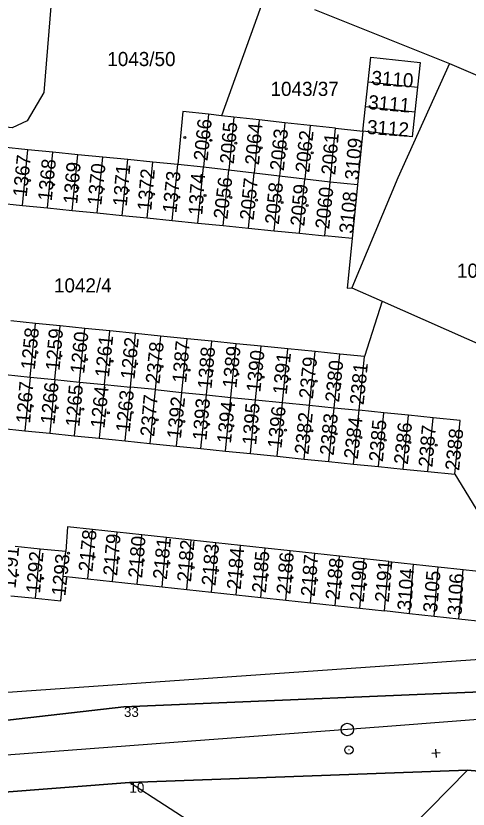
# Model space of a CAD drawing. Extents: x -779330 to -774454, y -1144748 to -1142831.
# Drawn here: x -775151 to -775096.6, y -1144462.2 to -1144366.8 of the extents above; entities that cross this region are included whole.
import ezdxf

# ---------------------------------------------------------------- set-up
doc = ezdxf.new("R2010")
doc.units = 0
for name, color, linetype in [('Hranice parcel', 7, 'Continuous'), ('Parcelní čísla', 7, 'Continuous'), ('SŽDC', 7, 'Continuous'), ('Vrstva 1', 7, 'Continuous'), ('Vrstva 53', 7, 'Continuous'), ('Vrstva 60', 7, 'Continuous'), ('Vrstva 7', 7, 'Continuous'), ('Značky budov', 7, 'Continuous')]:
    doc.layers.add(name, color=color, linetype=linetype)

msp = doc.modelspace()

# ---------------------------------------------------------------- linework, layer by layer
at = {"layer": 'Hranice parcel'}
for p, q in [((-775120.83, -1144363.72), (-775126.26, -1144378.82)), ((-775115.06, -1144366.03), (-775098.84, -1144372.52)), ((-775098.84, -1144372.52), (-775077.4, -1144381.72)), ((-775108.94, -1144377.72), (-775108.62, -1144374.75)), ((-775108.62, -1144374.75), (-775102.67, -1144375.4)), ((-775102.67, -1144375.4), (-775103, -1144378.37)), ((-775108.94, -1144377.72), (-775103, -1144378.37)), ((-775127.85, -1144378.65), (-775128.45, -1144385.01)), ((-775126.26, -1144378.82), (-775127.85, -1144378.65)), ((-775124.79, -1144378.98), (-775126.26, -1144378.82)), ((-775124.79, -1144378.98), (-775125.4, -1144385.37)), ((-775121.73, -1144379.32), (-775124.79, -1144378.98)), ((-775121.73, -1144379.32), (-775122.35, -1144385.72)), ((-775118.66, -1144379.66), (-775121.73, -1144379.32)), ((-775118.66, -1144379.66), (-775119.3, -1144386.08)), ((-775115.6, -1144379.99), (-775118.66, -1144379.66)), ((-775115.6, -1144379.99), (-775116.25, -1144386.44)), ((-775112.54, -1144380.33), (-775115.6, -1144379.99)), ((-775113.19, -1144386.79), (-775112.54, -1144380.33)), ((-775149.57, -1144382.91), (-775152.58, -1144382.61)), ((-775150.24, -1144389.6), (-775149.57, -1144382.91)), ((-775146.57, -1144383.21), (-775149.57, -1144382.91)), ((-775147.23, -1144389.91), (-775146.57, -1144383.21)), ((-775143.57, -1144383.51), (-775146.57, -1144383.21)), ((-775144.23, -1144390.21), (-775143.57, -1144383.51)), ((-775140.56, -1144383.81), (-775143.57, -1144383.51)), ((-775141.23, -1144390.51), (-775140.56, -1144383.81)), ((-775137.55, -1144384.1), (-775140.56, -1144383.81)), ((-775138.22, -1144390.81), (-775137.55, -1144384.1)), ((-775134.55, -1144384.4), (-775137.55, -1144384.1)), ((-775135.21, -1144391.11), (-775134.55, -1144384.4)), ((-775131.54, -1144384.7), (-775134.55, -1144384.4)), ((-775132.21, -1144391.42), (-775131.54, -1144384.7)), ((-775128.45, -1144385.01), (-775131.54, -1144384.7)), ((-775129.12, -1144391.73), (-775128.45, -1144385.01)), ((-775125.4, -1144385.37), (-775128.45, -1144385.01)), ((-775126.06, -1144392.03), (-775125.4, -1144385.37)), ((-775122.35, -1144385.72), (-775125.4, -1144385.37)), ((-775123.01, -1144392.34), (-775122.35, -1144385.72)), ((-775119.3, -1144386.08), (-775122.35, -1144385.72)), ((-775119.95, -1144392.65), (-775119.3, -1144386.08)), ((-775116.25, -1144386.44), (-775119.3, -1144386.08)), ((-775116.9, -1144392.95), (-775116.25, -1144386.44)), ((-775113.19, -1144386.79), (-775116.25, -1144386.44)), ((-775113.84, -1144393.26), (-775113.19, -1144386.79)), ((-775109.91, -1144387.13), (-775113.19, -1144386.79)), ((-775109.91, -1144387.13), (-775110.56, -1144393.59)), ((-775153.29, -1144389.3), (-775150.24, -1144389.6)), ((-775150.24, -1144389.6), (-775147.23, -1144389.91)), ((-775147.23, -1144389.91), (-775144.23, -1144390.21)), ((-775144.23, -1144390.21), (-775141.23, -1144390.51)), ((-775141.23, -1144390.51), (-775138.22, -1144390.81)), ((-775138.22, -1144390.81), (-775135.21, -1144391.11)), ((-775135.21, -1144391.11), (-775132.21, -1144391.42)), ((-775132.21, -1144391.42), (-775129.12, -1144391.73)), ((-775129.12, -1144391.73), (-775126.06, -1144392.03)), ((-775126.06, -1144392.03), (-775123.01, -1144392.34)), ((-775123.01, -1144392.34), (-775119.95, -1144392.65)), ((-775119.95, -1144392.65), (-775116.9, -1144392.95)), ((-775116.9, -1144392.95), (-775113.84, -1144393.26)), ((-775110.56, -1144393.59), (-775113.84, -1144393.26)), ((-775110.57, -1144399.52), (-775106.91, -1144401.13)), ((-775106.91, -1144401.13), (-775109.06, -1144407.78)), ((-775106.91, -1144401.13), (-775080.73, -1144412.7)), ((-775148.67, -1144403.79), (-775151.64, -1144403.5)), ((-775149.3, -1144410.25), (-775148.67, -1144403.79)), ((-775145.7, -1144404.09), (-775148.67, -1144403.79)), ((-775146.33, -1144410.55), (-775145.7, -1144404.09)), ((-775142.74, -1144404.39), (-775145.7, -1144404.09)), ((-775143.37, -1144410.85), (-775142.74, -1144404.39)), ((-775139.73, -1144404.69), (-775142.74, -1144404.39)), ((-775140.36, -1144411.15), (-775139.73, -1144404.69)), ((-775136.61, -1144405.01), (-775139.73, -1144404.69)), ((-775137.24, -1144411.46), (-775136.61, -1144405.01)), ((-775133.63, -1144405.31), (-775136.61, -1144405.01)), ((-775133.63, -1144405.31), (-775134.27, -1144411.76)), ((-775130.42, -1144405.63), (-775133.63, -1144405.31)), ((-775131.06, -1144412.09), (-775130.42, -1144405.63)), ((-775127.45, -1144405.93), (-775130.42, -1144405.63)), ((-775128.09, -1144412.39), (-775127.45, -1144405.93)), ((-775124.49, -1144406.23), (-775127.45, -1144405.93)), ((-775125.13, -1144412.69), (-775124.49, -1144406.23)), ((-775121.51, -1144406.53), (-775124.49, -1144406.23)), ((-775122.16, -1144412.99), (-775121.51, -1144406.53)), ((-775118.28, -1144406.85), (-775121.51, -1144406.53)), ((-775118.93, -1144413.31), (-775118.28, -1144406.85)), ((-775115.01, -1144407.18), (-775118.28, -1144406.85)), ((-775115.66, -1144413.64), (-775115.01, -1144407.18)), ((-775112.03, -1144407.48), (-775115.01, -1144407.18)), ((-775112.69, -1144413.94), (-775112.03, -1144407.48)), ((-775109.06, -1144407.78), (-775112.03, -1144407.48)), ((-775109.71, -1144414.24), (-775109.06, -1144407.78)), ((-775152.27, -1144409.95), (-775149.3, -1144410.25)), ((-775149.3, -1144410.25), (-775149.93, -1144416.7)), ((-775149.3, -1144410.25), (-775146.33, -1144410.55)), ((-775146.33, -1144410.55), (-775146.95, -1144417)), ((-775146.33, -1144410.55), (-775143.37, -1144410.85)), ((-775143.37, -1144410.85), (-775144, -1144417.3)), ((-775143.37, -1144410.85), (-775140.36, -1144411.15)), ((-775140.36, -1144411.15), (-775140.99, -1144417.6)), ((-775140.36, -1144411.15), (-775137.24, -1144411.46)), ((-775137.87, -1144417.92), (-775137.24, -1144411.46)), ((-775134.27, -1144411.76), (-775137.24, -1144411.46)), ((-775134.27, -1144411.76), (-775134.91, -1144418.22)), ((-775134.27, -1144411.76), (-775131.06, -1144412.09)), ((-775131.7, -1144418.54), (-775131.06, -1144412.09)), ((-775131.06, -1144412.09), (-775128.09, -1144412.39)), ((-775128.74, -1144418.85), (-775128.09, -1144412.39)), ((-775128.09, -1144412.39), (-775125.13, -1144412.69)), ((-775125.77, -1144419.15), (-775125.13, -1144412.69)), ((-775125.13, -1144412.69), (-775122.16, -1144412.99)), ((-775122.8, -1144419.45), (-775122.16, -1144412.99)), ((-775122.16, -1144412.99), (-775118.93, -1144413.31)), ((-775119.58, -1144419.77), (-775118.93, -1144413.31)), ((-775118.93, -1144413.31), (-775115.66, -1144413.64)), ((-775116.31, -1144420.1), (-775115.66, -1144413.64)), ((-775115.66, -1144413.64), (-775112.69, -1144413.94)), ((-775113.34, -1144420.4), (-775112.69, -1144413.94)), ((-775112.69, -1144413.94), (-775109.71, -1144414.24)), ((-775110.37, -1144420.71), (-775109.71, -1144414.24)), ((-775106.74, -1144414.54), (-775109.71, -1144414.24)), ((-775107.39, -1144421.01), (-775106.74, -1144414.54)), ((-775103.77, -1144414.84), (-775106.74, -1144414.54)), ((-775104.42, -1144421.31), (-775103.77, -1144414.84)), ((-775100.8, -1144415.14), (-775103.77, -1144414.84)), ((-775101.45, -1144421.61), (-775100.8, -1144415.14)), ((-775152.89, -1144416.4), (-775149.93, -1144416.7)), ((-775149.93, -1144416.7), (-775146.95, -1144417)), ((-775146.95, -1144417), (-775144, -1144417.3)), ((-775144, -1144417.3), (-775140.99, -1144417.6)), ((-775140.99, -1144417.6), (-775137.87, -1144417.92)), ((-775137.87, -1144417.92), (-775134.91, -1144418.22)), ((-775134.91, -1144418.22), (-775131.7, -1144418.54)), ((-775131.7, -1144418.54), (-775128.74, -1144418.85)), ((-775128.74, -1144418.85), (-775125.77, -1144419.15)), ((-775125.77, -1144419.15), (-775122.8, -1144419.45)), ((-775122.8, -1144419.45), (-775119.58, -1144419.77)), ((-775119.58, -1144419.77), (-775116.31, -1144420.1)), ((-775116.31, -1144420.1), (-775113.34, -1144420.4)), ((-775113.34, -1144420.4), (-775110.37, -1144420.71)), ((-775110.37, -1144420.71), (-775107.39, -1144421.01)), ((-775107.39, -1144421.01), (-775104.42, -1144421.31)), ((-775104.42, -1144421.31), (-775101.45, -1144421.61)), ((-775101.45, -1144421.61), (-775098.18, -1144421.94)), ((-775098.18, -1144421.94), (-775093.37, -1144429.8)), ((-775142.37, -1144434.51), (-775141.82, -1144428.58)), ((-775138.85, -1144428.9), (-775141.82, -1144428.58)), ((-775139.39, -1144434.83), (-775138.85, -1144428.9)), ((-775135.87, -1144429.22), (-775138.85, -1144428.9)), ((-775136.41, -1144435.15), (-775135.87, -1144429.22)), ((-775132.9, -1144429.54), (-775135.87, -1144429.22)), ((-775133.43, -1144435.48), (-775132.9, -1144429.54)), ((-775129.92, -1144429.86), (-775132.9, -1144429.54)), ((-775148.11, -1144430.93), (-775151.09, -1144430.63)), ((-775130.46, -1144435.8), (-775129.92, -1144429.86)), ((-775126.95, -1144430.18), (-775129.92, -1144429.86)), ((-775127.48, -1144436.12), (-775126.95, -1144430.18)), ((-775123.97, -1144430.5), (-775126.95, -1144430.18)), ((-775124.5, -1144436.44), (-775123.97, -1144430.5)), ((-775121, -1144430.82), (-775123.97, -1144430.5)), ((-775148.65, -1144436.85), (-775148.11, -1144430.93)), ((-775145, -1144431.23), (-775148.11, -1144430.93)), ((-775145.35, -1144434.19), (-775145, -1144431.23)), ((-775121.52, -1144436.76), (-775121, -1144430.82)), ((-775118.02, -1144431.14), (-775121, -1144430.82)), ((-775118.54, -1144437.09), (-775118.02, -1144431.14)), ((-775115.05, -1144431.46), (-775118.02, -1144431.14)), ((-775115.56, -1144437.41), (-775115.05, -1144431.46)), ((-775112.07, -1144431.78), (-775115.05, -1144431.46)), ((-775112.58, -1144437.73), (-775112.07, -1144431.78)), ((-775109.09, -1144432.1), (-775112.07, -1144431.78)), ((-775109.61, -1144438.05), (-775109.09, -1144432.1)), ((-775106.12, -1144432.42), (-775109.09, -1144432.1)), ((-775106.63, -1144438.37), (-775106.12, -1144432.42)), ((-775106.12, -1144432.42), (-775103.14, -1144432.74)), ((-775103.65, -1144438.7), (-775103.14, -1144432.74)), ((-775103.14, -1144432.74), (-775100.17, -1144433.06)), ((-775100.67, -1144439.02), (-775100.17, -1144433.06)), ((-775100.17, -1144433.06), (-775097.19, -1144433.38)), ((-775097.69, -1144439.34), (-775097.19, -1144433.38)), ((-775145.35, -1144434.19), (-775142.37, -1144434.51)), ((-775142.37, -1144434.51), (-775139.39, -1144434.83)), ((-775139.39, -1144434.83), (-775136.41, -1144435.15)), ((-775136.41, -1144435.15), (-775133.43, -1144435.48)), ((-775133.43, -1144435.48), (-775130.46, -1144435.8)), ((-775130.46, -1144435.8), (-775127.48, -1144436.12)), ((-775127.48, -1144436.12), (-775124.5, -1144436.44)), ((-775124.5, -1144436.44), (-775121.52, -1144436.76)), ((-775151.64, -1144436.56), (-775148.65, -1144436.85)), ((-775121.52, -1144436.76), (-775118.54, -1144437.09)), ((-775118.54, -1144437.09), (-775115.56, -1144437.41)), ((-775115.56, -1144437.41), (-775112.58, -1144437.73)), ((-775112.58, -1144437.73), (-775109.61, -1144438.05)), ((-775109.61, -1144438.05), (-775106.63, -1144438.37)), ((-775103.65, -1144438.7), (-775106.63, -1144438.37)), ((-775100.67, -1144439.02), (-775103.65, -1144438.7)), ((-775097.69, -1144439.34), (-775100.67, -1144439.02)), ((-775096.64, -1144457.51), (-775137.35, -1144459.01)), ((-775113.36, -1144474.42), (-775096.64, -1144457.51)), ((-775096.64, -1144457.51), (-775076.86, -1144459.23)), ((-775115.39, -1144473.12), (-775137.35, -1144459.01))]:
    msp.add_line(p, q, dxfattribs=at)
for points in [[(-775145.88, -1144354.35), (-775147.65, -1144376.02), (-775149.68, -1144379.44), (-775151.47, -1144380.29), (-775171.96, -1144377.97), (-775176.33, -1144377.47)], [(-775098.84, -1144372.52), (-775105.05, -1144386.27), (-775110.57, -1144399.52)], [(-775108.62, -1144374.75), (-775108.29, -1144371.77), (-775102.34, -1144372.43), (-775102.67, -1144375.4)], [(-775103, -1144378.37), (-775103.33, -1144381.34), (-775109.27, -1144380.69), (-775108.94, -1144377.72)], [(-775127.85, -1144378.65), (-775130.91, -1144378.31), (-775131.54, -1144384.7)], [(-775112.54, -1144380.33), (-775109.27, -1144380.69), (-775109.91, -1144387.13)], [(-775110.56, -1144393.59), (-775111.16, -1144399.56), (-775110.57, -1144399.52)], [(-775098.18, -1144421.94), (-775097.53, -1144415.47), (-775100.8, -1144415.14)], [(-775141.82, -1144428.58), (-775144.8, -1144428.26), (-775145, -1144431.23)], [(-775097.19, -1144433.38), (-775094.22, -1144433.7), (-775094.71, -1144439.66), (-775097.69, -1144439.34)], [(-775148.65, -1144436.85), (-775145.62, -1144437.15), (-775145.35, -1144434.19)], [(-775157.8, -1144448.55), (-775092.84, -1144444.02), (-775088.47, -1144442.87)], [(-775088.39, -1144447.82), (-775138.01, -1144449.91), (-775170.99, -1144453.66), (-775254.16, -1144459.9)], [(-775137.35, -1144459.01), (-775201.24, -1144463.92), (-775204.62, -1144464.16)]]:
    msp.add_lwpolyline(points, dxfattribs=at)
at = {"layer": 'SŽDC'}
for points in [[(-774890.46, -1144432.61), (-774957.77, -1144437.47), (-775003.31, -1144440.57), (-775006.9, -1144440.82), (-775032.95, -1144440.83), (-775037.63, -1144440.85), (-775036.16, -1144437.94), (-775069.78, -1144440.38), (-775071.04, -1144440.88), (-775088.39, -1144447.82), (-775138.01, -1144449.91), (-775170.99, -1144453.66), (-775254.16, -1144459.9), (-775301.48, -1144461.27), (-775337.71, -1144460.89), (-775341.64, -1144460.83), (-775351.35, -1144460.68), (-775377.95, -1144459.1), (-775417.93, -1144456.81), (-775426.17, -1144455.72)], [(-775425.39, -1144464.15), (-775389.68, -1144468.46), (-775332.79, -1144469.99), (-775289.7, -1144468.96), (-775237.91, -1144466.56), (-775217.76, -1144465.11), (-775204.62, -1144464.16), (-775201.24, -1144463.92), (-775137.35, -1144459.01), (-775096.64, -1144457.51), (-775076.86, -1144459.23), (-775049.08, -1144458.29), (-775047.73, -1144454.47), (-775006.07, -1144448.84), (-774942.23, -1144444.12), (-774919.16, -1144442.27)]]:
    msp.add_lwpolyline(points, dxfattribs=at)
at = {"layer": 'Vrstva 1'}
msp.add_lwpolyline([(-774830.163, -1144431.482), (-774850.563, -1144433.022), (-774864.475, -1144434.064), (-774869.912, -1144434.473), (-774871.827, -1144434.617), (-774885.853, -1144435.682), (-774900.88, -1144436.804), (-774924.49, -1144438.587), (-774948.039, -1144440.364), (-774972.389, -1144442.197), (-774996.531, -1144444.018), (-775020.057, -1144445.789), (-775040.384, -1144447.314), (-775053.937, -1144448.326), (-775072.564, -1144449.732), (-775089.145, -1144450.956), (-775106.822, -1144452.299), (-775129.866, -1144454.038), (-775154.332, -1144455.872), (-775163.87, -1144456.589), (-775186.746, -1144458.314), (-775211.372, -1144460.168), (-775237.518, -1144462.13)], dxfattribs=at)
at = {"layer": 'Vrstva 53'}
for points in [[(-775426.17, -1144455.72), (-775417.93, -1144456.81), (-775377.95, -1144459.1), (-775351.35, -1144460.68), (-775341.64, -1144460.83), (-775337.71, -1144460.89), (-775301.48, -1144461.27), (-775254.16, -1144459.9), (-775170.99, -1144453.66), (-775138.01, -1144449.91), (-775088.39, -1144447.82), (-775071.04, -1144440.88), (-775069.78, -1144440.38), (-775036.16, -1144437.94), (-775037.63, -1144440.85), (-775032.95, -1144440.83), (-775006.9, -1144440.82), (-775003.31, -1144440.57), (-774957.77, -1144437.47), (-774890.46, -1144432.61)], [(-775426.17, -1144455.72), (-775417.93, -1144456.81), (-775377.95, -1144459.1), (-775351.35, -1144460.68), (-775341.64, -1144460.83), (-775337.71, -1144460.89), (-775301.48, -1144461.27), (-775254.16, -1144459.9), (-775170.99, -1144453.66), (-775138.01, -1144449.91), (-775088.39, -1144447.82), (-775071.04, -1144440.88), (-775069.78, -1144440.38), (-775036.16, -1144437.94), (-775037.63, -1144440.85), (-775032.95, -1144440.83), (-775006.9, -1144440.82), (-775003.31, -1144440.57), (-774957.77, -1144437.47), (-774890.46, -1144432.61)], [(-774919.16, -1144442.27), (-774942.23, -1144444.12), (-775006.07, -1144448.84), (-775047.73, -1144454.47), (-775049.08, -1144458.29), (-775076.86, -1144459.23), (-775096.64, -1144457.51), (-775137.35, -1144459.01), (-775201.24, -1144463.92), (-775204.62, -1144464.16), (-775217.76, -1144465.11), (-775237.91, -1144466.56), (-775289.7, -1144468.96), (-775332.79, -1144469.99)], [(-774919.16, -1144442.27), (-774942.23, -1144444.12), (-775006.07, -1144448.84), (-775047.73, -1144454.47), (-775049.08, -1144458.29), (-775076.86, -1144459.23), (-775096.64, -1144457.51), (-775137.35, -1144459.01), (-775201.24, -1144463.92), (-775204.62, -1144464.16), (-775217.76, -1144465.11), (-775237.91, -1144466.56), (-775289.7, -1144468.96), (-775332.79, -1144469.99)]]:
    msp.add_lwpolyline(points, dxfattribs=at)
at = {"layer": 'Vrstva 60'}
for p, q in [((-775138.01, -1144449.91), (-775138.01, -1144449.91)), ((-775096.64, -1144457.51), (-775096.64, -1144457.51)), ((-775137.35, -1144459.01), (-775137.35, -1144459.01))]:
    msp.add_line(p, q, dxfattribs=at)
at = {"layer": 'Vrstva 7'}
for p, q in [((-775110.89, -1144455.082), (-775110.99, -1144455.09)), ((-775099.939, -1144455.441), (-775100.937, -1144455.517)), ((-775100.4, -1144455.978), (-775100.476, -1144454.98))]:
    msp.add_line(p, q, dxfattribs=at)
for centre, radius in [((-775111.125, -1144452.624), 0.75), ((-775110.94, -1144455.086), 0.5)]:
    msp.add_circle(centre, radius, dxfattribs=at)
at = {"layer": 'Značky budov'}
for centre in [(-775130.685, -1144381.439), (-775127.565, -1144381.779), (-775124.535, -1144382.129), (-775121.505, -1144382.679), (-775118.475, -1144382.809), (-775115.355, -1144383.279), (-775149.395, -1144386.619), (-775146.485, -1144387.109), (-775143.585, -1144387.479), (-775140.515, -1144387.649), (-775137.505, -1144387.809), (-775134.445, -1144388.239), (-775131.425, -1144388.609), (-775128.255, -1144388.399), (-775125.135, -1144388.659), (-775122.065, -1144388.959), (-775118.985, -1144389.259), (-775115.955, -1144389.599), (-775148.485, -1144407.299), (-775145.615, -1144407.709), (-775142.505, -1144408.119), (-775139.455, -1144408.349), (-775136.515, -1144408.659), (-775133.435, -1144408.959), (-775130.185, -1144409.399), (-775127.415, -1144409.479), (-775124.315, -1144409.909), (-775121.275, -1144410.259), (-775118.075, -1144410.499), (-775114.865, -1144410.739), (-775112.015, -1144411.109), (-775149.065, -1144413.729), (-775146.055, -1144413.939), (-775142.975, -1144414.109), (-775139.895, -1144414.549), (-775137.025, -1144414.509), (-775134.015, -1144415.389), (-775130.795, -1144415.599), (-775127.825, -1144415.929), (-775124.915, -1144416.099), (-775121.875, -1144416.509), (-775118.565, -1144416.639), (-775115.385, -1144416.709), (-775112.485, -1144417.079), (-775109.485, -1144417.509), (-775106.555, -1144417.819), (-775103.615, -1144418.129), (-775100.435, -1144418.439), (-775144.685, -1144431.419), (-775141.655, -1144431.879), (-775138.655, -1144432.069), (-775135.705, -1144432.319), (-775132.625, -1144432.619), (-775129.675, -1144433.139), (-775126.755, -1144433.519), (-775150.835, -1144434.049), (-775147.835, -1144434.449), (-775123.775, -1144434.039), (-775120.775, -1144434.059), (-775117.805, -1144434.369), (-775114.845, -1144434.679), (-775111.945, -1144435.059), (-775108.945, -1144435.209)]:
    msp.add_circle(centre, 0.117, dxfattribs=at)

# ---------------------------------------------------------------- texts
at = {"layer": 'Parcelní čísla'}
for s, p in [('1043/50', (-775140.02, -1144372.85)), ('1043/37', (-775120.37, -1144376.44)), ('1043/36', (-775097.93, -1144398.3)), ('1042/4', (-775146.44, -1144400.07))]:
    msp.add_text(s, height=1.7, dxfattribs=at).set_placement(p)
for s, rotation, p in [('3110', 356, (-775108.27, -1144375.093)), ('3111', 355, (-775108.671, -1144378.008)), ('2066', 84, (-775127.954, -1144384.308)), ('2065', 85, (-775124.793, -1144384.674)), ('2064', 85, (-775121.763, -1144384.804)), ('3112', 356, (-775108.81, -1144381.003)), ('2063', 84, (-775118.774, -1144385.498)), ('2062', 84, (-775115.704, -1144385.718)), ('2061', 85, (-775112.583, -1144386.004)), ('3109', 85, (-775109.751, -1144386.601)), ('1367', 84, (-775149.724, -1144388.648)), ('1368', 84, (-775146.714, -1144389.128)), ('1369', 85, (-775143.643, -1144389.494)), ('1370', 84, (-775140.744, -1144389.668)), ('1371', 85, (-775137.673, -1144389.764)), ('1372', 85, (-775134.723, -1144390.304)), ('1373', 84, (-775131.704, -1144390.588)), ('1374', 86, (-775128.582, -1144390.829)), ('2056', 83, (-775125.566, -1144391.323)), ('2057', 84, (-775122.404, -1144391.438)), ('2058', 84, (-775119.374, -1144391.948)), ('2059', 85, (-775116.303, -1144392.154)), ('2060', 84, (-775113.314, -1144392.508)), ('3108', 84, (-775110.436, -1144393.052)), ('1258', 84, (-775148.754, -1144409.418)), ('1259', 85, (-775145.773, -1144409.514)), ('1260', 84, (-775142.804, -1144409.898)), ('1261', 84, (-775139.824, -1144410.338)), ('1262', 84, (-775136.744, -1144410.578)), ('2378', 84, (-775133.734, -1144411.118)), ('1387', 85, (-775130.523, -1144411.004)), ('1388', 85, (-775127.473, -1144411.714)), ('1389', 84, (-775124.484, -1144411.638)), ('1390', 84, (-775121.604, -1144412.128)), ('1391', 84, (-775118.424, -1144412.408)), ('2379', 84, (-775115.274, -1144412.928)), ('2380', 84, (-775112.124, -1144413.338)), ('2381', 84, (-775109.164, -1144413.648)), ('1267', 85, (-775149.323, -1144415.884)), ('1266', 84, (-775146.384, -1144415.988)), ('1265', 85, (-775143.373, -1144416.274)), ('1264', 84, (-775140.364, -1144416.458)), ('1263', 84, (-775137.324, -1144416.938)), ('2377', 85, (-775134.373, -1144417.464)), ('1392', 84, (-775131.164, -1144417.718)), ('1393', 85, (-775128.083, -1144417.904)), ('1394', 84, (-775125.144, -1144418.288)), ('1395', 85, (-775122.103, -1144418.474)), ('1396', 84, (-775119.054, -1144418.868)), ('2382', 84, (-775115.804, -1144419.608)), ('2383', 84, (-775112.774, -1144419.728)), ('2384', 83, (-775109.876, -1144420.173)), ('2385', 85, (-775106.843, -1144420.484)), ('2386', 84, (-775103.844, -1144420.808)), ('2387', 85, (-775100.883, -1144421.134)), ('2388', 84, (-775097.674, -1144421.558)), ('2178', 84, (-775141.814, -1144433.718)), ('2179', 85, (-775138.843, -1144434.194)), ('2180', 85, (-775135.833, -1144434.464)), ('2181', 84, (-775132.864, -1144434.648)), ('2182', 85, (-775129.943, -1144434.934)), ('2183', 85, (-775126.993, -1144435.394)), ('1291', 85, (-775151.063, -1144435.724)), ('1292', 85, (-775148.123, -1144436.324)), ('1293', 84, (-775145.064, -1144436.628)), ('2184', 85, (-775123.963, -1144435.854)), ('2185', 85, (-775120.933, -1144436.264)), ('2186', 85, (-775117.983, -1144436.414)), ('2187', 85, (-775115.053, -1144436.694)), ('2188', 84, (-775112.094, -1144437.108)), ('2190', 85, (-775109.153, -1144437.374)), ('2191', 85, (-775106.133, -1144437.374)), ('3104', 86, (-775103.426, -1144438.35)), ('3105', 85, (-775100.331, -1144438.631)), ('3106', 87, (-775097.372, -1144438.938))]:
    msp.add_text(s, height=1.7, rotation=rotation, dxfattribs=at).set_placement(p)
at = {"layer": 'Vrstva 60'}
for s, p in [('33', (-775138.01, -1144451.11)), ('10', (-775137.35, -1144460.21))]:
    msp.add_text(s, height=1.2, dxfattribs=at).set_placement(p)

doc.saveas('drawing.dxf')
